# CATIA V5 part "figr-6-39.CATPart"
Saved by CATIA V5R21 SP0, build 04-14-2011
Part number: Part1
Bounding box of the stored display mesh (mm): x -42.494 to 42.494, y -51.186 to 51.186, z 0 to 35
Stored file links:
  D:\CATIA V5R21 E-RESOURCES\CATIA-V5R21\catia-v5r21-prt\c06-catia-v5r21-prt\c06-catia-v5r21-figr-6-39.CATPart
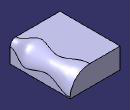
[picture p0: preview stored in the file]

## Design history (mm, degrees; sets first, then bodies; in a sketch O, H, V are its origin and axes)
Set1
  Point1: type OnCurve, Support edge [face of Pad1 | face of Pad1], Length 25.019
  Point2: type OnCurve, Support edge [face of Pad1 | face of Pad1], Length 63.062
Body1 (main body)
  Sketch1 on xy-plane, origin (0, 0, 0), H (1, 0, 0), V (0, 1, 0)
    line L1 (-42.4944, 51.1864) -> (42.4944, 51.1864)
    line L2 (42.4944, 51.1864) -> (42.4944, -51.1864)
    line L3 (42.4944, -51.1864) -> (-42.4944, -51.1864)
    line L4 (-42.4944, -51.1864) -> (-42.4944, 51.1864)
    axis line L5 (42.4944, -51.1864) -> (-42.4944, 51.1864)
    horizontal: L1 H, L3 H
    vertical: L2 V, L4 V
    midpoint: O L5
  Pad1: profile Sketch1, direction (0, 0, 1), length 35
  Fillet1: on edge [face of Pad1 | face of Pad1]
